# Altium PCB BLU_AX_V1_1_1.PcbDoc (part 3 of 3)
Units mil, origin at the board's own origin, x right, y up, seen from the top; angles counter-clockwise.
Board outline 2623.2 x 4215 mil, 6 copper layers (Top Layer, GND1, PWR, Signal Inner, GND2, Bottom Layer), stack 76.535 mil thick; 238 components, 119 nets, 699 pads, 786 vias.
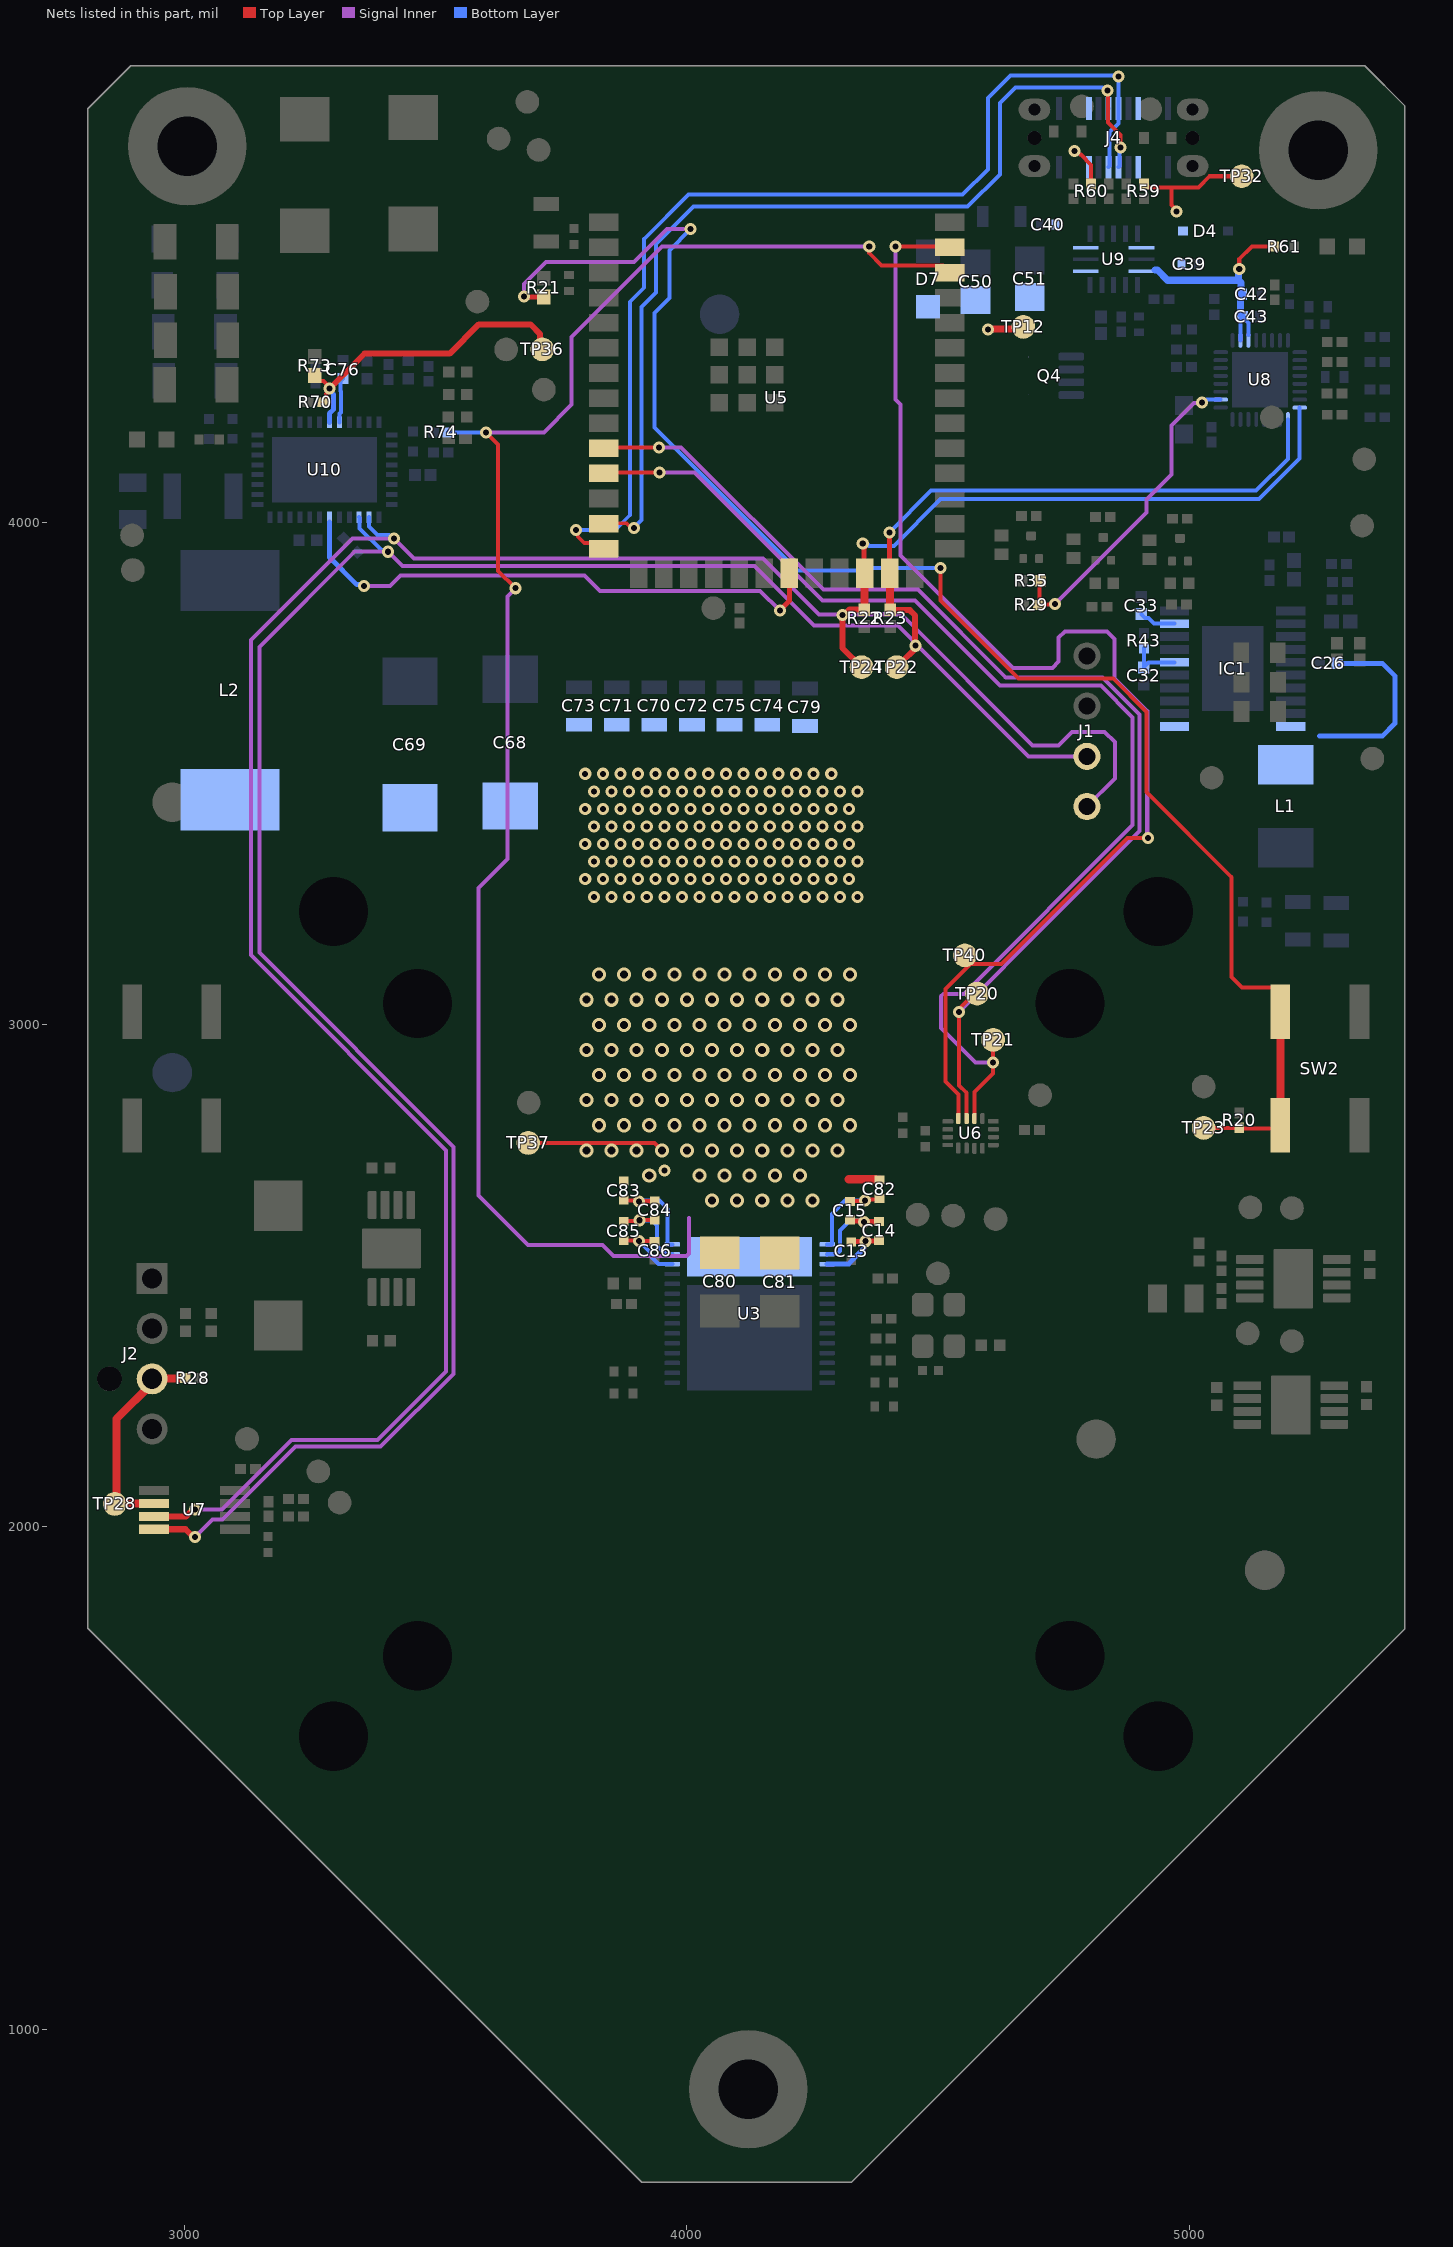
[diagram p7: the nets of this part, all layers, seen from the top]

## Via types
v1: diameter 24, hole 12, Top Layer to Bottom Layer, tented both sides, 623 vias
v2: diameter 28, hole 16, Top Layer to Bottom Layer, 146 vias
v3: diameter 19.68, hole 7.87, Top Layer to Bottom Layer, 16 vias
v4: diameter 24, hole 12, Top Layer to Bottom Layer, 1 vias

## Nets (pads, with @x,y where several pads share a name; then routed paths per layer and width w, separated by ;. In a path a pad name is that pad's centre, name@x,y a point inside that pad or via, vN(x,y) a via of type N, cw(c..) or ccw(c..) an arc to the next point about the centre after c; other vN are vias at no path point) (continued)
RST: TP40.1 U5.39 U6.12 | length 2553.2
  Top Layer w8: v1(4415,4550) 4522.48,4550 U5.39@4523.43,4549.06 ; U6.12@4540.43,2813.48 4540.43,2861.58 4515.3,2886.72 4515.3,3071.3 TP40.1@4564.95,3120.96 ; TP40.1@4553.75,3138.41 4553.75,3132.16 TP40.1@4564.95,3120.96 ; v1(4918.17,3372.49) 4877.8,3372.49 4626.26,3120.96 TP40.1@4564.95,3120.96
  Signal Inner w8: v1(4415,4550) 4415,4245.34 4424.91,4235.43 4424.91,3935.09 4649.29,3710.71 4727.88,3710.71 4740.47,3723.3 4740.47,3771.03 4752.82,3783.38 4836.62,3783.38 4851.79,3768.21 4851.79,3689.98 4916.79,3624.98 4916.79,3373.87 v1(4918.17,3372.49)
RST_IN: R20.1 R21.2 SW2.1 SW2.2 TP23.1 | length 3249.9
  Top Layer w8: v1(4505,3909.64) 4505,3845.17 4660.78,3689.39 4849.07,3689.39 4915.02,3623.44 4915.02,3463.9 5085,3293.91 5085,3095 5105.83,3074.17 5168.13,3074.17 5181.81,3060.48 SW2.2@5181.81,3026.03 ; TP23.1@5029.17,2794.7 5029.32,2794.85 5099.85,2794.85 R20.1@5100,2795 5101.43,2793.57 5175.74,2793.57 SW2.1@5181.81,2799.65
  Top Layer w10: v1(3675.72,4450.34) 3676.19,4449.87 3714.31,4449.87 R21.2@3714.79,4449.4
  Top Layer w16: SW2.1@5181.81,2799.65 SW2.2@5181.81,3026.03
  Signal Inner w8: v1(3675.72,4450.34) 3675.72,4475.72 3719.16,4519.16 3894.16,4519.16 3959.91,4584.91 v1(4007.58,4584.91)
  Bottom Layer w8: v1(4007.58,4584.91) 3965,4542.34 3965,4447.81 3935,4417.81 3935,4190 4220,3905 4358.01,3905 4362.66,3909.64 v1(4505,3909.64)
RX: TP21.1 U5.11 U6.10 | length 2360.1
  Top Layer w8: U5.11@3834.45,4099.06 3835.39,4100 v1(3945,4100) ; U6.10@4572.49,2813.48 4572.49,2865.77 4610,2903.29 v1(4610,2925) TP21.1@4610,2970
  Signal Inner w8: v1(3945,4100) 4015,4100 4270,3845 4453.83,3845 4623.36,3675.47 4824.53,3675.47 4887.54,3612.46 4887.54,3397.54 4551.6,3061.61 4510.97,3061.61 4506.28,3056.92 4506.28,2993.72 4575,2925 v1(4610,2925)
SCL: J1.3 R23.1 TP22.1 U5.25 U7.8 U8.9 U10.3 | length 5595.1
  Top Layer w10: U5.25@4403.67,3900.11 v1@4403.67,3980.63
  Top Layer w12: U7.8@2939.02,1995.4 3001.36,1995.4 3016.75,1980 v1(3020,1980) ; R23.1@4405,3826.73 4409.86,3826.73 4410.81,3825.78 4443.83,3825.78 4454.4,3815.21 4454.4,3755.6 v1(4455,3755) ; TP22.1@4420,3720 4425.35,3720 v1@4457.67,3752.33
  Top Layer w16: v1(4403.41,3980.89) v1@4403.67,3980.63 ; U5.25@4403.67,3900.11 4404.47,3899.31 4404.47,3827.26 R23.1@4405,3826.73
  Signal Inner w8: v1(3020,1980) 3055,2015 3075,2015 3220,2160 3390,2160 3535,2305 3535,2757.12 3148.35,3143.76 3148.35,3752.9 3338.48,3943.02 3403.43,3943.02 v1(3404.27,3942.19) 3433.09,3913.36 4134.96,3913.36 4253.35,3794.98 4420.82,3794.98 4448.93,3766.87 4448.93,3765.4 4455,3759.33 v1(4455,3755) 4459.33,3755 4465.86,3748.46 4466.41,3748.46 4680.56,3534.31 J1.3@4795.45,3534.31
  Bottom Layer w8: U10.3@3347.28,4011.02 3348.2,4010.1 3348.2,3988.39 3391.34,3945.25 3401.2,3945.25 v1(3404.27,3942.19) ; v1(4403.41,3980.89) 4486.29,4063.78 5133.78,4063.78 5196.86,4126.86 U8.9@5196.86,4205.72
SDA: J1.4 R22.1 TP24.1 U5.24 U7.7 U8.8 U10.2 | length 5892.8
  Top Layer w10: U5.24@4352.61,3901.17 v1@4352.61,3953.79
  Top Layer w12: U7.7@2939.02,2020.99 3002.74,2020.99 3016.75,2035 v1(3020,2035) ; v1(4309.68,3816.48) 4309.68,3750.47 TP24.1@4347.8,3712.34 ; v1@4310.17,3813.43 4323.5,3826.75 R22.1@4353.29,3826.75
  Top Layer w16: v1(4350.2,3958.37) 4350.2,3956.2 v1@4352.61,3953.79 ; U5.24@4352.61,3901.17 4353.94,3899.84 4353.62,3899.53 4353.62,3827.05 R22.1@4353.31,3826.73
  Signal Inner w8: v1(3020,2035) 3074.11,2035 3212.61,2173.5 3383.5,2173.5 3520,2310 3520,2750 3131.38,3138.62 3131.38,3766.38 3333.92,3968.92 v1(3416.74,3968.92) 3456.56,3929.1 4151.62,3929.1 4263.37,3817.36 4308.8,3817.36 v1(4309.68,3816.48) 4310.9,3817.71 4427.29,3817.71 4688.48,3556.52 4740.09,3556.52 4767.15,3583.57 4831.43,3583.57 4852.13,3562.87 4852.13,3490.99 J1.4@4795.45,3434.31
  Bottom Layer w8: U10.2@3366.97,4011.02 3366.5,4010.55 3366.5,3992.85 3384.22,3975.13 3406.2,3975.13 3412.41,3968.92 v1(3416.74,3968.92) ; v1(4350.2,3958.37) 4353.26,3955.31 4361.52,3955.31 4362.88,3953.94 4412.46,3953.94 4505.3,4046.78 5139.79,4046.78 5220.48,4127.48 U8.8@5220.48,4229.35
SINK_EN: R29.2 R35.1 U8.18 | length 675.5
  Top Layer w8: R35.1@4704,3884.43 4711.26,3877.16 4711.26,3876.86 R35.1@4703.7,3884.43 4702.18,3882.91 4702.18,3838.06 R29.2@4700.26,3836.15 4701.3,3837.18 4732.2,3837.18 v1(4733.23,3838.22)
  Signal Inner w8: v1(4733.23,3838.22) 4915,4019.99 4915,4045.93 4964.95,4095.88 4964.95,4193.46 5009.71,4238.22 5024.76,4238.22 v1(5025.88,4239.34)
  Bottom Layer w8: v1(5025.88,4239.34) 5029.55,4239.34 5035.3,4245.09 U8.18@5063,4245.09
SMB: U5.21 U10.6 | length 1110.7
  Top Layer w10: v1(4185,3825) 4185,3825.31 4203.94,3844.25 U5.21@4203.94,3899.84
  Signal Inner w8: v1(3356.89,3873.96) 3408.96,3873.96 3430,3895 3796.36,3895 3827.24,3864.11 4145.89,3864.11 v1(4185,3825)
  Bottom Layer w10: U10.6@3288.2,4000.97 3288.2,3931.1 3342.66,3876.64 3354.21,3876.64 v1(3356.89,3873.96)
SS: C33.1 IC1.19 | length 74.7
  Bottom Layer w8: C33.1@4905,3818.13 4905,3817.28 4912.27,3810.01 4918.97,3810.01 4930.15,3798.83 IC1.19@4971.19,3798.83
SW: C26.1 IC1.10 IC1.11 L1.1 | length 380.7
  Bottom Layer w10: 5260,3575 5385,3575 5410,3600 5410,3695 5385,3720 C26.1@5295,3720
TACH: J2.3 R28.1 TP28.1 U7.6 | length 424.8
  Top Layer w16: TP28.1@2860.47,2045.74 2863.64,2048.91 2863.64,2214.85 2935.63,2286.84 2935.63,2295.63 3000.37,2295.63 R28.1@3001,2296.27 ; TP28.1@2860.9,2046.65 2938.95,2046.65 U7.6@2939.02,2046.58
TPS_EN: R70.1 R73.2 TP36.1 U10.27 | length 648.4
  Top Layer w8: R73.2@3258.68,4293.41 3258.68,4292.43 3268.46,4282.65 3276.65,4282.65 3288.58,4270.72 v1(3288.58,4267.26) 3288.58,4262.93 3281.59,4255.94 3281.59,4245.84 3275.75,4240 R70.1@3274.76,4240
  Top Layer w12: v1(3288.58,4267.26) 3357.96,4336.64 3527.34,4336.64 3585.69,4395 3688.43,4395 3707.71,4375.73 3707.71,4349.8 TP36.1@3712.18,4345.33
  Bottom Layer w10: U10.27@3288.23,4200 3288.3,4200.08 3288.3,4217.87 3296.37,4225.94 3296.37,4255.25 3295.94,4255.68
TX: TP20.1 U5.10 U6.11 | length 2303
  Top Layer w8: U5.10@3834.45,4149.06 3835.19,4149.8 v1(3944.8,4149.8) ; U6.11@4556.97,2813.48 4556.64,2813.81 4556.64,2822.05 4556.37,2822.32 4556.37,2864.73 4541.45,2879.66 v1(4541.45,3025.98) 4544.51,3029.04 4544.51,3034.73 4572.13,3062.35 TP20.1@4577.82,3062.35
  Signal Inner w8: v1(3944.8,4149.8) 3945,4150 3988.43,4150 4271.58,3866.85 4460.13,3866.85 4634.99,3691.99 4828.01,3691.99 4901.6,3618.4 4901.6,3386.33 4724.46,3209.19 4724.46,3208.99 v1(4541.45,3025.98)
USB_N: J4.A7 J4.B7 U5.13 | length 1963.2
  Top Layer w7.49: U5.13@3834.45,3999.06 3879.89,3999.06 3889.74,3989.2 v1(3894.2,3989.2)
  Top Layer w8: v1(4837.66,4860.65) 4838.3,4860.01 4838.3,4796.7 4863.18,4771.82 v1(4863.18,4747.5)
  Bottom Layer w7.94: v1(3894.2,3989.2) 3910,4005 3910,4430 3938.83,4458.83 3938.83,4555.13 4013.27,4629.57 4559.14,4629.57 4623.12,4693.56 4623.12,4835.67 4654.18,4866.72 4827.24,4866.72 4830.24,4863.72 4834.59,4863.72 v1(4837.66,4860.65)
  Bottom Layer w8: v1(4837.66,4860.65) 4838.72,4859.59 4838.72,4826.02 J4.B7@4839.77,4824.97 ; J4.A7@4859.46,4708.04 4861.32,4709.9 4861.32,4745.64 v1(4863.18,4747.5)
USB_P: J4.A6 J4.B6 U5.14 | length 2107.6
  Top Layer w7.49: v1(3779.35,3985.05) 3782.51,3981.89 3782.51,3972.46 3795.38,3959.59 3823.92,3959.59 U5.14@3834.45,3949.06
  Bottom Layer w7.94: v1(3779.35,3985.05) 3856.36,3985.05 3886.17,4014.87 3886.17,4439.87 3915,4468.69 3915,4565 4003.4,4653.4 4549.27,4653.4 4599.3,4703.43 4599.3,4845.53 4644.31,4890.54 4827.24,4890.54 4857.06,4890.54 v1(4859.16,4888.44)
  Bottom Layer w8: J4.A6@4839.77,4708.04 4841.68,4709.94 4841.68,4777.79 4859.4,4795.51 J4.B6@4859.4,4824.39 ; J4.B6@4859.16,4825.27 v1(4859.16,4888.44)
V_eFuse: C42.1 C43.1 C50.1 C51.1 D7.1 Q4.7 R61.2 TP12.1 U8.26 U8.27 U9.8 U9.14 | length 539
  Top Layer w8: v1(5100,4505) 5100,4525 5125.04,4550.04 R61.2@5169.56,4550.04
  Top Layer w14: v1(4600,4385) 4600.99,4385.99 4665.99,4385.99 TP12.1@4670,4390
  Bottom Layer w8: U8.26@5102.37,4363.2 5102.44,4363.27 5102.44,4405.94 C43.1@5106.57,4410.08 5106.57,4409.99 5118.35,4398.21 5118.35,4374.14 U8.27@5118.19,4373.97
  Bottom Layer w14: 4931.79,4503.21 4937.14,4503.21 4957.47,4482.89 5098.36,4482.89 ; v1(5100,4505) 5098.36,4503.36 5098.36,4482.89 ; C43.1@5106.57,4410.08 5102.24,4414.41 5102.24,4450.94 C42.1@5106.3,4455 5103.05,4458.25 5103.05,4478.2 5098.36,4482.89
VBUS: C39.1 C40.1 D4.1 J4.A4 J4.A9 J4.B4 J4.B9 R59.2 R60.2 TP32.1 U9.6 U9.16 | length 342.3
  Top Layer w8: v1(4771.76,4740.26) 4776.09,4740.26 4783.02,4733.33 4784.49,4733.33 4805,4712.81 R60.2@4805,4674.76 ; R59.2@4910,4674.76 4910,4673.78 4915.84,4667.94 4965,4667.94 ; v1(4975,4620) 4975,4622.69 4965,4632.69 4965,4667.94 ; TP32.1@5105,4690 5040.8,4690 5018.73,4667.94 4965,4667.94
VCORE: C68.1 C69.1 C70.1 C71.1 C72.1 C73.1 C74.1 C75.1 C79.1 C80.2 C81.2 C82.2 C83.1 L2.2 R74.2 TP37.1 U3.31 U5.38 | length 3717
  Top Layer w8: v1(3600,4180) 3624.15,4155.85 3624.15,3903.79 v1(3658.42,3869.52) ; TP37.1@3684.04,2764.7 3935.3,2764.7 v2@3955,2745 ; v1(4363.13,4550.36) 4363.13,4536.87 4387.3,4512.7 4493.24,4512.7 4493.38,4512.56 4509.93,4512.56 U5.38@4523.43,4499.06
  Top Layer w17: 4322.7,2692.73 4375.61,2692.73 4376.48,2691.87 4383.16,2691.87 C82.2@4383.52,2691.51
  Signal Inner w8: v1(3600,4180) 3715,4180 3770,4235 3770,4370 3950.36,4550.36 v1(4363.13,4550.36) ; v1(3658.42,3869.52) 3642.33,3853.43 3642.33,3330.32 3584.87,3272.87 3584.87,2660.07 3683.34,2561.6 3831.81,2561.6 3853.51,2539.9 3999.48,2539.9 4004.17,2544.59 4004.17,2615
  Bottom Layer w8: R74.2@3524.53,4180 v1(3600,4180)
  other v1: 3955,2710 3815,3255 3850,3255 3885,3255 3920,3255 3955,3255 3990,3255 4025,3255 4060,3255 4095,3255 4130,3255 4165,3255 4200,3255 4235,3255 4270,3255 4305,3255 4340,3255 3797.5,3290 3832.5,3290 3867.5,3290 3902.5,3290 3937.5,3290 3972.5,3290 4007.5,3290 4042.5,3290 4077.5,3290 4112.5,3290 4147.5,3290 4182.5,3290 4217.5,3290 4252.5,3290 4287.5,3290 4322.5,3290 3815,3325 3850,3325 3885,3325 3920,3325 3955,3325 3990,3325 4025,3325 4060,3325 4095,3325 4130,3325 4165,3325 4200,3325 4235,3325 4270,3325 4305,3325 4340,3325 3797.5,3360 3832.5,3360 3867.5,3360 3902.5,3360 3937.5,3360 3972.5,3360 4007.5,3360 4042.5,3360 4077.5,3360 4112.5,3360 4147.5,3360 4182.5,3360 4217.5,3360 4252.5,3360 4287.5,3360 4322.5,3360 3815,3395 3850,3395 3885,3395 3920,3395 3955,3395 3990,3395 4025,3395 4060,3395 4095,3395 4130,3395 4165,3395 4200,3395 4235,3395 4270,3395 4305,3395 4340,3395 3797.5,3430 3832.5,3430 3867.5,3430 3902.5,3430 3937.5,3430 3972.5,3430 4007.5,3430 4042.5,3430 4077.5,3430 4112.5,3430 4147.5,3430 4182.5,3430 4217.5,3430 4252.5,3430 4287.5,3430 4322.5,3430 3815,3465 3850,3465 3885,3465 3920,3465 3955,3465 3990,3465 4025,3465 4060,3465 4095,3465 4130,3465 4165,3465 4200,3465 4235,3465 4270,3465 4305,3465 4340,3465 3797.5,3500 3832.5,3500 3867.5,3500 3902.5,3500 3937.5,3500 3972.5,3500 4007.5,3500 4042.5,3500 4077.5,3500 4112.5,3500 4147.5,3500 4182.5,3500 4217.5,3500 4252.5,3500 4287.5,3500
  other v2: 4050,2650 4100,2650 4150,2650 4200,2650 4250,2650 3925,2700 4025,2700 4075,2700 4125,2700 4175,2700 4225,2700 3800,2750 3850,2750 3900,2750 3950,2750 4000,2750 4050,2750 4100,2750 4150,2750 4200,2750 4250,2750 4300,2750 3825,2800 3875,2800 3925,2800 3975,2800 4025,2800 4075,2800 4125,2800 4175,2800 4225,2800 4275,2800 4325,2800 3800,2850 3850,2850 3900,2850 3950,2850 4000,2850 4050,2850 4100,2850 4150,2850 4200,2850 4250,2850 4300,2850 3825,2900 3875,2900 3925,2900 3975,2900 4025,2900 4075,2900 4125,2900 4175,2900 4225,2900 4275,2900 4325,2900 3800,2950 3850,2950 3900,2950 3950,2950 4000,2950 4050,2950 4100,2950 4150,2950 4200,2950 4250,2950 4300,2950 3825,3000 3875,3000 3925,3000 3975,3000 4025,3000 4075,3000 4125,3000 4175,3000 4225,3000 4275,3000 4325,3000 3800,3050 3850,3050 3900,3050 3950,3050 4000,3050 4050,3050 4100,3050 4150,3050 4200,3050 4250,3050 4300,3050 3825,3100 3875,3100 3925,3100 3975,3100 4025,3100 4075,3100 4125,3100 4175,3100 4225,3100 4275,3100 4325,3100
VDD1_1: C15.2 C82.1 U3.1 | length 208.6
  Top Layer w8: C15.2@4324.57,2648.38 4325.28,2649.09 4354.21,2649.09 4357.08,2651.96 4381.37,2651.96 C82.1@4383.52,2654.11
  Bottom Layer w8: U3.1@4279.17,2562.8 4288.12,2562.8 4288.55,2563.22 4288.55,2623.55 4315,2650 4354.73,2650 v1(4354.93,2649.81)
VDD1_2: C14.2 C15.1 U3.2 | length 185.4
  Top Layer w10: C15.1@4324.57,2610.98 4326.28,2609.27 4351.29,2609.27 v1(4353,2607.55) 4353.29,2607.84 4381.05,2607.84 C14.2@4382.03,2608.81
  Bottom Layer w8: U3.2@4279.17,2543.11 4279.6,2543.54 4298.54,2543.54 4305,2550 4305,2590 4325,2610 4350.56,2610 v1(4353,2607.55)
VDD1_3: C13.2 C14.1 U3.3 | length 158.8
  Top Layer w10: C13.2@4327.32,2567.75 4327.96,2568.38 4354.83,2568.38 4356.31,2569.87 4381.86,2569.87 C14.1@4382.71,2570.72
  Bottom Layer w10: U3.3@4279.17,2523.43 4279.74,2524 4322.38,2524 4352.78,2554.39 4352.78,2566.34 v1(4355.46,2569.02)
VDD2_1: C83.2 C84.1 U3.30 | length 207.9
  Top Layer w8: C83.2@3874.3,2651.32 3875.84,2649.78 3902.71,2649.78 v1(3904.25,2648.24) 3904.67,2648.66 3935.5,2648.66 C84.1@3935.91,2649.07
  Bottom Layer w8: v1(3904.25,2648.24) 3906.01,2650 3945,2650 3961.45,2633.55 3961.45,2563.22 3961.88,2562.8 U3.30@3970.83,2562.8
VDD2_2: C84.2 C85.1 U3.29 | length 179.4
  Top Layer w8: C85.1@3874.42,2609.33 3874.51,2609.43 3903.97,2609.43 3905.79,2611.25 3935.5,2611.25 C84.2@3935.91,2611.67
  Bottom Layer w8: v1(3905.37,2610.83) 3905.58,2610.63 3929.37,2610.63 3940,2600 3940,2560 3951.13,2548.87 3953.91,2548.87 3959.67,2543.11 U3.29@3970.83,2543.11
VDD2_3: C85.2 C86.1 U3.28 | length 152.2
  Top Layer w8: C85.2@3874.26,2570.62 3874.63,2570.25 3904.25,2570.25 3905.21,2569.29 3935.09,2569.29 C86.1@3935.67,2568.71
  Bottom Layer w8: v1(3904.63,2569.87) 3925.46,2549.04 3925.46,2541.2 3943.24,2523.43 U3.28@3970.83,2523.43
VDD5: C76.1 U10.28 | length 90.8
  Bottom Layer w8: U10.28@3307.91,4200 3308.27,4200.38 3308.27,4217.34 3310.87,4219.93 3310.87,4261.69 3310.08,4262.48 3310.08,4282.28 C76.1@3315,4287.2
VDD_MP: C32.1 IC1.16 R43.2 | length 103.4
  Bottom Layer w8: C32.1@4910,3711.87 C32.1@4910,3712.72 ; R43.2@4910,3750.24 C32.1@4910,3712.72 ; IC1.16@4971.19,3722.06 4919.34,3722.06 C32.1@4910,3712.72
pads on no net: FD1.0 FD2.0 FD3.0 FD4.0 FD5.0 FD6.0 IC1.9 IC1.12 IC1.17 J2. J4. J4.A8 J4.B8 Q4.2 Q4.3 U1.3 U1.7 U2.3 U2.7 U3.12 U3.19 U4.3 U4.7 U5.4 U5.5 U5.6 U5.7 U5.8 U5.9 U5.12 U5.16 U5.17 U5.18 U5.20 U5.22 U5.26 U5.28 U5.29 U5.30 U5.31 U5.32 U5.33 U5.34 U5.35 U6.9 U9.5 U10.35 U10.36 U10.38 U10.39 U10.40

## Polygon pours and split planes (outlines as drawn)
DGND on Top Layer "pour" (solid, pour order 65): 2870,3665 2870,1835 3960,745 4275,745 5390,1860 5390,2955 5250,3095 4930,3095 4375,3650
DGND on Top Layer "NONET_L-01_P-001" (solid, pour order 47): 5119.65,3603.36 5036.64,3603.36 5015,3625 5015,3805 5135,3805 5148.13,3791.87 5148.13,3613.13 5140,3605
VCORE on Top Layer "NONET_L-01_P-001" (solid, pour order 57): 3999.2,2578.72 3999.54,2578.37 3999.54,2500.28 4249.17,2500.28 4248.83,2500.62 4248.83,2610.56 4369.78,2731.51 4369.78,3466.51 4289.78,3546.51 3764.78,3546.51 3764.78,2746.51 3829.78,2681.51 3954.78,2681.51 3979.78,2656.51 3979.78,2599.27 3999.57,2579.47
DGND on Top Layer "NONET_L-01_P-001" (solid, pour order 54): 4001.09,2273.43 3866.09,2138.43 3866.09,1930 4396.09,1930 4396.09,2143.43 4251.09,2288.43 4251.09,2473.43 4241.09,2483.43 4011.09,2483.43 4001.09,2473.43
3V3_IN on Top Layer "NONET_L-01_P-001" (solid, pour order 0): 3030,4225 3030,4575 3095,4640 3510,4640 3530,4620 3530,4535 3510,4515 3510,4410 3490,4390 3220,4390 3220,4280 3240,4260 3255,4260 3260,4255 3260,4225 3255,4220 3255,4190 3165,4190 3155,4200 3055,4200
3V3_IN on Top Layer "NONET_L-01_P-001" (solid, pour order 42): 5160,3765 5160,3605 5260,3605 5275,3590 5360,3590 5395,3625 5395,3690 5310,3690 5305,3695 5305,3740 5285,3740 5285,3715 5260,3715 5210,3765 5190,3765
3V3_IN on Top Layer "NONET_L-01_P-001" (solid, pour order 25): 3310,2610 3275,2645 3275,2730 3305,2760 3375,2760 3385,2750 3385,2610
DGND on Top Layer "NONET_L-01_P-001" (solid, pour order 24): 2895,2455 2950,2455 2990,2415 3060,2415 3155,2510 3475,2510 3485,2520 3485,2590 3475,2600 3295,2600 3245,2650 3245,2700 3240,2705 3130,2705 3110,2685 3110,2600 3055,2545 2900,2545 2880,2525 2880,2470
1V2 on Top Layer "NONET_L-01_P-001" (solid, pour order 15): 5080,2525 5075,2530 5055,2530 5030,2555 4985,2555 4975,2565 4975,2610 4995,2630 5075,2630 5105,2600 5140,2600 5150,2590 5150,2525
DGND on Top Layer "NONET_L-01_P-001" (solid, pour order 22): 3565,4855 3545,4875 2920,4875 2845,4800 2845,4140 2865,4120 2915,4120 2935,4140 2935,4195 2965,4225 2990,4225 2990,4575 3085,4670 3510,4670 3565,4725
FS on Top Layer "NONET_L-01_P-001" (solid, pour order 21): 3350,2500 3305,2455 3130,2455 3100,2425 3100,2410 3090,2400 2990,2400 2955,2435 2910,2435 2890,2415 2890,2375 2915,2350 2970,2350 2990,2370 3080,2370 3105,2345 3380,2345 3395,2360 3395,2410 3410,2425 3410,2500
DGND on Top Layer "NONET_L-01_P-001" (solid, pour order 20): 4040,4210 4065,4185 4225,4185 4240,4200 4240,4365 4225,4380 4040,4380
DGND on Top Layer "NONET_L-01_P-001" (solid, pour order 19): 4410,4580 4385,4605 4385,4620 4555,4620 4555,4580
3V3_ESP on Top Layer "NONET_L-01_P-001" (solid, pour order 18): 3635,4530 3605,4560 3605,4620 3620,4635 3670,4635 3675,4630 3675,4575
3V3_ESP on Top Layer "NONET_L-01_P-001" (solid, pour order 16): 3895,4530 3635,4530 3630,4535 3630,4585 3740,4585 3760,4565 3800,4565 3805,4570 3885,4570 3895,4560
DGND on Top Layer "NONET_L-01_P-001" (solid, pour order 17): 3895,4580 3795,4580 3790,4575 3765,4575 3740,4600 3690,4600 3685,4605 3685,4665 3868.33,4665 3895,4625
3V3_ESP on Top Layer "NONET_L-01_P-001" (solid, pour order 14): 5266.32,2584.93 5281.32,2599.93 5391.32,2599.93 5406.32,2584.93 5406.32,2534.93 5391.32,2519.93 5331.32,2519.93 5326.32,2524.93 5266.32,2524.93
0V8_REF on Top Layer "NONET_L-01_P-001" (solid, pour order 13): 5065,2265 4995,2265 4975,2285 4975,2335 4995,2355 5120,2355 5145,2330 5145,2270 5075,2270
3V3_ESP on Top Layer "NONET_L-01_P-001" (solid, pour order 12): 5265,2330 5280,2345 5390,2345 5405,2330 5405,2280 5390,2265 5330,2265 5325,2270 5265,2270
DGND on Top Layer "NONET_L-01_P-001" (solid, pour order 11): 4526.63,2780.67 4526.4,2780.91 4503.21,2780.91 4489.85,2767.55 4465.01,2767.55 4463.08,2765.63 4463.08,2706.92 4465,2705 4498.19,2705 4530,2736.8 4530,2780.55
DGND on Bottom Layer "pour" (solid, pour order 68): 2870,3665 2870,1835 3960,745 4275,745 5390,1860 5390,2955 5250,3095 4930,3095 4375,3650
DGND on Bottom Layer "NONET_L-01_P-001" (solid, pour order 64): 4745,4800 4665,4800 4655,4810 4655,4845 4665,4855 4745,4855
3V3_IN on Bottom Layer "NONET_L-01_P-001" (solid, pour order 1): 3255,4185 3160,4185 3155,4190 3155,4195 3030,4195 3030,4575 3095,4640 3480,4640 3505,4615 3505,4405 3495,4395 3235,4395 3235,4265 3245,4255 3255,4255 3255,4210
DGND on Bottom Layer "NONET_L-01_P-001" (solid, pour order 61): 5009.16,4505.55 5009.54,4505.94 5009.54,4612.94 4979.33,4643.15 4961.57,4643.15 4951.27,4653.45 4951.27,4664.51 5064.79,4664.51 5068.39,4660.91 5068.39,4615.09 5073.8,4615.09 5100.57,4588.32 5100.57,4553.06 5052.43,4504.92 5031.32,4504.92
3V3_IN on Bottom Layer "NONET_L-01_P-001" (solid, pour order 60): 4675,4075 4915,4075 4945,4105 4945,4205 4950,4210 5015,4210 5015,4245 5025,4255 5025,4265 4875,4265 4840,4230 4735,4230 4725,4240 4715,4230 4670,4230
DGND on Bottom Layer "NONET_L-01_P-001" (solid, pour order 45): 5170,3215 5175,3210 5175,3195 5185,3185 5380,3185 5390,3175 5390,3085 5380,3075 5090,3075 5075,3090 5075,3200 5090,3215
3V3_ESP on Bottom Layer "NONET_L-01_P-001" (solid, pour order 59): 5080,3415 4975,3415 4965,3405 4965,3355 4970,3350 5005,3350 5035,3320 5035,3295 5055,3275 5080,3275
VCORE on Bottom Layer "NONET_L-01_P-001" (solid, pour order 56): 3999.42,2577.2 3999.76,2576.86 3999.76,2498.77 4249.39,2498.77 4249.05,2499.11 4249.05,2609.05 4370,2730 4370,3465 4290,3545 3765,3545 3765,2745 3830,2680 3955,2680 3980,2655 3980,2597.76 3999.8,2577.96
DGND on Bottom Layer "NONET_L-01_P-001" (solid, pour order 53): 4000,2270 3865,2135 3865,1930 4395,1930 4395,2140 4250,2285 4250,2470 4240,2480 4010,2480 4000,2470
3V3_IN on Bottom Layer "NONET_L-01_P-001" (solid, pour order 51): 4723.51,4286.94 4560,4286.94 4560,4075 4675,4075 4725,4125 4725,4225
3V3_IN on Bottom Layer "NONET_L-01_P-001" (solid, pour order 46): 5175,3705 5295,3705 5305,3695 5385,3695 5395,3685 5395,3625 5355,3585 5280,3585 5245,3620 5245,3635 5175,3635
3V3_ESP on Bottom Layer "NONET_L-01_P-001" (solid, pour order 44): 5185,3225 5185,3205 5195,3195 5360,3195 5370,3205 5370,3240 5200,3240
3V3_ESP on Bottom Layer "NONET_L-01_P-001" (solid, pour order 43): 5055,3275 5055,3410 5060,3415 5360,3415 5385,3390 5385,3255 5355,3225 5105,3225
SW on Bottom Layer "NONET_L-01_P-001" (solid, pour order 41): 4940,3605 5250,3605 5265,3590 5265,3470 5250,3455 5130,3455 5055,3530 4940,3530
DGND on Bottom Layer "NONET_L-01_P-001" (solid, pour order 40): 4942.28,3705.18 4942.46,3705 5010,3705 5020,3715 5050,3715 5050,3630 5045,3625 5015,3625 5003.73,3636.27 4941.62,3636.27
DGND on Bottom Layer "NONET_L-01_P-001" (solid, pour order 39): 5141.9,4195.39 5141.9,4235.39 5146.9,4240.39 5166.9,4240.39 5171.9,4235.39 5171.9,4190.39 5166.9,4185.39 5146.9,4185.39
DGND on Bottom Layer "NONET_L-01_P-001" (solid, pour order 38): 5079.13,4192.45 5079.13,4219.13 5085,4225 5085,4240 5115,4240 5125,4230 5125,4185 5080,4185
DGND on Bottom Layer "NONET_L-01_P-001" (solid, pour order 36): 5130,4470 5155,4470 5155,4325 5130,4325
V_eFuse on Bottom Layer "NONET_L-01_P-001" (solid, pour order 35): 4884.67,4493.86 4950,4490 4947.2,4507.2 4932.93,4512.72 4930.54,4515.11 4923.04,4515.11
V_eFuse on Bottom Layer "NONET_L-01_P-001" (solid, pour order 34): 4938.47,4515 4745,4515 4730,4500 4730,4485 4720,4475 4465,4475 4450,4460 4450,4310 4462.43,4297.57 4727.57,4297.57 4730,4300 4730,4355 4775,4355 4795,4375 4795,4430 4785,4440 4785,4491.45 4795,4490 4805.18,4490 4880.14,4490
DGND on Bottom Layer "NONET_L-01_P-001" (solid, pour order 33): 4951.88,4802.54 5043.01,4802.54 5055,4814.53 5055,4855 5050,4860 4955,4860 4950,4855
DGND on Bottom Layer "NONET_L-01_P-001" (solid, pour order 31): 4650,4495 4650,4670 4660,4680 4695,4680 4710,4665 4710,4495
DGND on Bottom Layer "NONET_L-01_P-001" (solid, pour order 30): 4746.89,4731.64 4746.29,4732.24 4652.24,4732.24 4645,4725 4645,4675 4655,4665 4733.34,4665 4747.04,4678.7
DGND on Bottom Layer "NONET_L-01_P-001" (solid, pour order 29): 4946.94,4735 5055,4735 5070,4720 5070,4660 5065,4655 4960,4655 4946.94,4668.06
VBUS on Bottom Layer "NONET_L-01_P-001" (solid, pour order 26): 4970,4533.16 4970,4505 5005,4505 5005,4610 4980,4635 4950,4635 4945,4640 4945,4850 4940,4855 4895,4855 4890,4850 4890,4620 4900,4610 4920,4610 4925,4605 4925,4575 4905,4555 4870,4555 4870,4533.16
VBUS on Bottom Layer "NONET_L-01_P-001" (solid, pour order 27): 4905.36,4533.33 4741.67,4533.33 4725,4550 4725,4655 4740,4655 4760,4675 4760,4855 4765,4860 4804.66,4860 4810,4854.66 4804.66,4690 4790,4615 4790,4565 4790,4555 4905.36,4555
BP1V5 on Bottom Layer "NONET_L-01_P-001" (solid, pour order 23): 3330,3940 3345,3925 3345,3910 3373.33,3881.67 3410,3880 3408.12,3916.87 3380,3945 3355,3945 3343.92,3956.08
DGND on Bottom Layer "NONET_L-01_P-001" (solid, pour order 10): 4260,3655 3740,3655 3740,3635 3685,3580 3405,3580 3345,3640 3345,3805 3395,3855 3825,3855 3920,3760 4260,3760
VCORE on Bottom Layer "NONET_L-01_P-001" (solid, pour order 8): 3350,3385 3440,3295 4220,3295 4320,3395 4320,3620 4305,3635 3755,3635 3710,3590 3710,3570 3385,3570 3275,3680 2875,3680 2840,3645 2840,3410 2865,3385
NetC55_2 on Bottom Layer "NONET_L-01_P-001" (solid, pour order 7): 3255,4025 3255,3995 3245,3985 3245,3755 3215,3725 2900,3725 2840,3785 2840,4000 2865,4025 3148.26,4025 3161.67,4035 3250,4035
DGND on Bottom Layer "NONET_L-01_P-001" (solid, pour order 2): 3010,4000 3010,4120 2865,4120 2845,4140 2845,4805 2915,4875 3540,4875 3565,4850 3565,4755 3510,4700 3130,4700 3050,4620 3005,4620 2990,4605 2990,4205 3015,4180 3150,4180 3155,4175 3160,4175 3160,4060 3130,4030 3130,4000
DGND on Bottom Layer "NONET_L-01_P-001" (solid, pour order 3): 3155,4025 3155,4027.83 3167.17,4040 3385,4040 3390,4045 3390,4170 3385,4175 3157.5,4175 3152.5,4180 3130,4180 3130,4030
AGND on Bottom Layer "NONET_L-01_P-001" (solid, pour order 4): 3345,4310 3390,4310 3395,4305 3470,4305 3475,4300 3540,4300 3560,4280 3560,4225 3590,4225 3615,4200 3615,4160 3566.64,4107.05 3481.77,4107.05 3481.77,4083.43 3638.43,4083.43 3660,4105 3660,4315 3585,4390 3345,4390
NetC66_2 on Bottom Layer "NONET_L-01_P-001" (solid, pour order 6): 2870,4110 2990,4110 3000,4100 3000,4000 2995,3995 2960,3995 2955,4000 2955,4045 2950,4050 2865,4050 2860,4055 2860,4105
DGND on Signal Inner "NONET_L-01_P-001" (solid, pour order 71): 3660,3800 3660,3320 3610,3270 3610,2675 3710,2575 4015,2575 4040,2550 4040,2295 3965,2220 3865,2220 3865,1925 3915,1875 3914.93,1874.93 3914.93,1664.93 3815,1565 3815,1230 4015,1030 4540,1030 5375,1865 5375,4815 5310,4880 4595,4880 4595,4840 4595,4815 4595,4675 4470,4550 4095,4550 4095,4505 3670,4080 3670,4005
DGND on Signal Inner "NONET_L-01_P-001" (solid, pour order 70): 3580,3855 2985,3855 2840,3710 2840,1835 3360,1315 3720,1315 3765,1360 3765,2315 3540,2540 3540,3300 3600,3360 3600,3828.33
VCORE on Signal Inner "NONET_L-01_P-001" (solid, pour order 62): 3999.21,2578.7 3999.55,2578.36 3999.55,2500.27 4249.18,2500.27 4248.84,2500.61 4248.84,2610.55 4369.79,2731.5 4369.79,3466.5 4289.79,3546.5 3764.79,3546.5 3764.79,2746.5 3829.79,2681.5 3954.79,2681.5 3979.79,2656.5 3979.79,2599.26 3999.59,2579.46
DGND on GND2 (split plane): 3815,4691.13 3623.07,4691.13 3621.9,4690.89 3620.9,4690.23 3577.84,4647.16 3577.17,4646.17 3576.94,4645 3576.94,4535 3577.17,4533.83 3577.84,4532.84 3629.7,4480.97 3630.7,4480.31 3631.87,4480.08 4200.6,4480.08 4255.98,4424.7 4255.98,4341.27 4256.21,4340.1 4256.29,4339.97 4256.29,4327.85 4256.53,4326.68 4257.19,4325.68 4258.18,4325.02 4259.35,4324.79 5197.85,4324.79 5199.02,4325.02 5200.01,4325.68 5201.94,4327.62 5201.94,3480 5201.94,3476.27 5168.73,3443.06 4915,3443.06 4913.83,3442.83 4912.84,3442.16 4897.84,3427.16 4897.17,3426.17 4896.94,3425 4896.94,3335 4897.17,3333.83 4897.84,3332.84 4912.84,3317.84 4913.83,3317.17 4915,3316.94 4973.73,3316.94 5026.94,3263.73 5026.94,3260 5027.17,3258.83 5027.84,3257.84 5057.84,3227.84 5058.83,3227.17 5060,3226.94 5409.9,3226.94 5409.9,1805.43 4319.57,715.1 3918.32,715.1 2826.9,1806.53 2826.9,4816.11 2900.69,4889.9 3815,4889.9
3V3_ESP on GND2 (split plane): 3815,4660 4380.67,4660 4402.84,4637.84 4537.84,4502.84 4538.83,4502.17 4540,4501.94 5378.73,4501.94 5409.9,4470.77 5409.9,3234.23 5408.73,3233.06 5061.27,3233.06 5033.06,3261.27 5033.06,3265 5032.83,3266.17 5032.16,3267.16 4977.16,3322.16 4976.17,3322.83 4975,3323.06 4916.27,3323.06 4903.06,3336.27 4903.06,3423.73 4916.27,3436.94 5170,3436.94 5171.17,3437.17 5172.16,3437.84 5207.16,3472.84 5207.83,3473.83 5208.06,3475 5208.06,3480 5208.06,4335 5207.83,4336.17 5207.16,4337.16 5206.17,4337.83 5205,4338.06 5203.83,4337.83 5202.84,4337.16 5196.58,4330.91 4262.41,4330.91 4262.41,4340.95 4262.18,4342.12 4262.09,4342.25 4262.09,4425.96 4261.86,4427.14 4261.2,4428.13 4204.03,4485.3 4203.04,4485.96 4201.87,4486.19 3633.13,4486.19 3583.06,4536.27 3583.06,4643.73 3624.33,4685.01 3815,4685.01
VCORE on GND2 (split plane): 4302.84,3532.84 4303.83,3532.17 4305,3531.94 4308.73,3531.94 4371.94,3468.73 4371.94,3390 4371.94,2736.27 4327.84,2692.16 4252.84,2617.16 4252.17,2616.17 4251.94,2615 4251.94,2506.27 4248.73,2503.06 4003.06,2503.06 4003.06,2580 4002.83,2581.17 4002.16,2582.16 3983.06,2601.27 3983.06,2655 3982.83,2656.17 3982.16,2657.16 3957.16,2682.16 3956.17,2682.83 3955,2683.06 3826.27,2683.06 3763.06,2746.27 3763.06,3546.94 4288.73,3546.94
DGND on GND2 (split plane): 5409.9,4821.68 5409.9,4479.42 5382.16,4507.16 5381.17,4507.83 5380,4508.06 4541.27,4508.06 4407.16,4642.16 4389.33,4660 4545,4660 4545,4889.9 5341.68,4889.9
3V3_ESP on PWR (split plane): 5409.9,4821.68 5409.9,1805.43 4319.57,715.1 3918.32,715.1 2826.9,1806.53 2826.9,4816.11 2900.69,4889.9 3815,4889.9 3815,4660 4545,4660 4545,4889.9 5341.68,4889.9
3V3_IN on PWR (split plane): 3812.84,4517.84 3813.83,4517.17 3815,4516.94 4193.73,4516.94 4317.84,4392.84 4318.83,4392.17 4320,4391.94 4721.94,4391.94 4721.94,4305 4721.94,4240 4722.17,4238.83 4722.84,4237.84 4732.84,4227.84 4733.83,4227.17 4735,4226.94 4840.5,4226.94 4841.67,4227.17 4842.66,4227.84 4875.54,4260.71 4941.94,4260.71 4941.94,4071.27 4928.73,4058.06 4915,4058.06 4913.83,4057.83 4912.84,4057.16 4897.84,4042.16 4897.17,4041.17 4896.94,4040 4896.94,3966.37 4897.17,3965.2 4897.84,3964.2 5019.2,3842.84 5020.2,3842.17 5021.37,3841.94 5115.93,3841.94 5250.04,3707.84 5251.03,3707.17 5252.2,3706.94 5382.8,3706.94 5382.8,3582.12 5378.73,3578.06 5210.18,3578.06 5170.01,3618.23 5169.02,3618.89 5167.85,3619.12 5025.2,3619.12 4878.06,3766.27 4878.06,3770 4877.83,3771.17 4877.16,3772.16 4847.16,3802.16 4846.17,3802.83 4845,3803.06 4721.27,3803.06 4567.16,3957.16 4467.16,4057.16 4466.17,4057.83 4465,4058.06 3826.27,4058.06 3642.16,4242.16 3498.19,4386.14 3497.2,4386.8 3496.03,4387.03 3223.17,4387.03 3221.99,4386.8 3221,4386.14 3220.34,4385.14 3220.11,4383.97 3220.11,4281.83 3220.34,4280.66 3221,4279.67 3242.84,4257.84 3243.83,4257.17 3245,4256.94 3253.73,4256.94 3256.94,4253.73 3256.94,4226.27 3252.84,4222.16 3252.17,4221.17 3251.94,4220 3251.94,4193.06 3166.27,4193.06 3157.16,4202.16 3156.17,4202.83 3155,4203.06 3056.27,4203.06 3052.16,4207.16 3033.06,4226.27 3033.06,4573.73 3042.16,4582.84 3096.27,4636.94 3693.73,4636.94
DGND on PWR (split plane): 4251.49,2287.41 4251.72,2286.24 4252.39,2285.25 4272.01,2265.62 4272.24,2265.47 4298.96,2238.74 4299.19,2238.6 4345.16,2192.62 4346.06,2192.02 4386.45,2151.64 4386.45,2151.63 4396.94,2141.14 4396.94,1938.06 3863.06,1938.06 3863.06,2115 3863.06,2133.73 3922.16,2192.84 3982.16,2252.84 3998.46,2269.13 3999.12,2270.13 3999.36,2271.3 3999.36,2479.67 3999.42,2480.01 3999.42,2483.23 4251.49,2483.23
VCORE on PWR (split plane): 4369.29,3467.68 4369.29,3452.72 4369.29,2731.34 4361.11,2723.16 4360.19,2722.97 4359.2,2722.31 4269.72,2632.83 4268.62,2632.61 4267.62,2631.95 4247.84,2612.16 4247.17,2611.17 4246.94,2610 4246.94,2503.06 4003.06,2503.06 4003.06,2575 4002.83,2576.17 4002.16,2577.16 3992.16,2587.16 3983.06,2596.27 3983.06,2655 3982.83,2656.17 3982.16,2657.16 3957.16,2682.16 3956.17,2682.83 3955,2683.06 3831.27,2683.06 3812.16,2702.16 3763.06,2751.27 3763.06,2780 3763.06,3546.94 4290.04,3546.94
1V2 on PWR (split plane): 4562.84,2787.84 4563.83,2787.17 4565,2786.94 4688.73,2786.94 4696.94,2778.73 4696.94,2745 4697.17,2743.83 4697.84,2742.84 4798.72,2641.96 4799.71,2641.29 4800.88,2641.06 5084.61,2641.06 5086.94,2638.73 5086.94,2421.27 5060.08,2394.41 4744.74,2394.41 4743.57,2394.17 4742.57,2393.51 4497.12,2148.06 4401.02,2148.06 4377.65,2171.43 4377.02,2172.37 4342.23,2207.16 4342.04,2207.29 4313.06,2236.27 4313.06,2275 4312.83,2276.17 4312.16,2277.16 4293.06,2296.27 4293.06,2436.94 4340,2436.94 4341.17,2437.17 4342.16,2437.84 4402.16,2497.84 4402.83,2498.83 4403.06,2500 4403.06,2528.73 4407.16,2532.84 4407.83,2533.83 4408.06,2535 4408.06,2673.73 4448.92,2714.59 4449.58,2715.58 4449.81,2716.75 4449.81,2825.49 4471.27,2846.94 4503.73,2846.94
DGND on GND1 (split plane): 5409.9,4821.68 5409.9,1805.43 4319.57,715.1 3918.32,715.1 2826.9,1806.53 2826.9,4816.11 2900.69,4889.9 3815,4889.9 3815,4660 4545,4660 4545,4889.9 5341.68,4889.9
VCORE on GND1 (split plane): 4318.87,3518.16 4319.86,3517.5 4320.22,3517.43 4369.32,3468.33 4369.32,2731.12 4333.74,2695.55 4333.39,2695.48 4332.4,2694.82 4253.07,2615.49 4252.45,2614.57 4249.38,2611.49 4248.72,2610.5 4248.49,2609.33 4248.49,2503.86 4000.34,2503.86 4000.34,2577.72 4000.11,2578.89 3999.44,2579.88 3978.06,2601.27 3978.06,2660 3977.83,2661.17 3977.16,2662.16 3957.16,2682.16 3956.17,2682.83 3955,2683.06 3830.17,2683.06 3825.76,2687.47 3825.46,2687.92 3781.56,2731.81 3780.66,2732.42 3769.2,2743.88 3768.89,2744.33 3765.17,2748.06 3765.17,3546.94 4290.09,3546.94

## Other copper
Top Layer:
  region: 3967.5,1652.89 3965.3,1654.69 3963.11,1655.69 3959.92,1656.88 3958.72,1658.08 3957.92,1658.48 3957.12,1659.28 3953.53,1661.27 3951.54,1663.27 3950.74,1663.67 3949.74,1664.27 3949.34,1665.06 3945.35,1669.05 3944.96,1669.85 3943.16,1672.05 3942.56,1672.25 3942.16,1673.04 3940.17,1676.63 3938.17,1679.43 3937.57,1681.62 3936.58,1684.21 3934.98,1685.81 3934.18,1687.81 3932.79,1693.99 3932.19,1696.18 3930.59,1701.37 3930.19,1702.97 3929.79,1712.94 3929.6,1840.81 3930.59,1842.21 3932.79,1842.81 3937.97,1842.41 3981.06,1842.01 3981.66,1841.41 3982.06,1839.82 3981.66,1835.83 3982.06,1724.91 3982.46,1723.71 3982.86,1718.53 3983.46,1715.53 3985.45,1712.34 3987.45,1707.16 3990.04,1704.56 3991.64,1701.77 3995.03,1699.58 3996.22,1698.38 3997.02,1697.98 4003.01,1694.79 4005.8,1693.59 4015.77,1693.19 4023.75,1693.59 4024.95,1693.99 4027.15,1694.59 4029.54,1696.18 4034.53,1697.98 4035.92,1698.98 4036.32,1699.77 4036.92,1700.37 4039.71,1701.97 4041.51,1703.76 4041.91,1704.56 4042.51,1705.16 4043.3,1705.56 4044.3,1706.56 4046.3,1710.15 4047.49,1711.35 4047.89,1712.14 4048.69,1714.14 4049.29,1716.73 4050.29,1718.93 4051.88,1724.51 4052.28,1726.11 4052.08,1840.81 4053.08,1842.21 4055.27,1842.81 4061.66,1842.41 4103.75,1842.61 4104.95,1841.81 4105.34,1840.22 4105.15,1834.43 4105.34,1660.68 4104.95,1659.48 4105.34,1654.29 4104.35,1652.1 4102.75,1651.7 4095.17,1652.1 4054.48,1652.5 4053.88,1653.09 4053.48,1654.69 4053.68,1660.08 4053.48,1672.64 4053.88,1673.84 4053.48,1681.02 4052.48,1682.02 4049.69,1681.62 4048.29,1680.22 4047.69,1677.63 4046.89,1675.64 4046.3,1675.04 4045.9,1674.24 4044.3,1672.64 4042.31,1669.05 4041.31,1668.06 4040.51,1667.66 4039.51,1666.66 4039.11,1665.86 4037.72,1664.47 4036.92,1664.07 4033.73,1660.87 4032.93,1660.48 4030.14,1658.88 4028.14,1656.88 4026.15,1656.09 4021.76,1653.69 4019.76,1652.89 4018.17,1652.5 4015.38,1652.1 4013.78,1651.7 4011.19,1650.7 4008.99,1649.7 4007.4,1649.3 4002.41,1648.71 3985.45,1648.51 3984.26,1648.91 3981.26,1649.5 3979.67,1649.9 3977.87,1650.5 3975.68,1651.1 3973.68,1651.5 3972.09,1651.9 3969.69,1652.3 3968.1,1652.7 3967.9,1652.89
  region: 3884.91,1904.65 3896.68,1904.85 3898.67,1904.05 3899.47,1903.25 3899.87,1901.66 3899.67,1896.27 3899.87,1660.28 3899.47,1659.08 3899.87,1655.09 3899.47,1653.09 3898.87,1652.5 3895.68,1651.7 3890.5,1652.1 3851.2,1651.9 3849.2,1652.7 3848.4,1653.49 3848,1655.09 3848.4,1660.28 3848.2,1901.86 3848.8,1903.25 3850.2,1904.65 3852.99,1905.05 3856.98,1904.65 3884.51,1904.65
  region: 142 vertices and 2 holes, not listed, extent 3630.96,1651.7 3826.86,1905.05
  region: 343 vertices and 0 holes, not listed, extent 4056.67,1542.78 4382.63,1889.49
  region: 594 vertices and 0 holes, not listed, extent 4313.21,1543.18 4639.18,1908.24
GND1 (plane layer: these items are gaps in the copper):
  region: 4545,4910 4545,4660 3815,4660 3815,4910
  lines w6: 3762.11,2746.79 3762.11,3550 4291.35,3550 4321.03,3520.32 4321.65,3520.32 4372.38,3469.59 4372.38,2729.85 4335.17,2692.65 4334.56,2692.65 4255.24,2613.33 4255.24,2613.02 4251.55,2609.33 4251.55,2501.55 4250.8,2500.8 3997.28,2500.8 3997.28,2577.72 3975,2600 3975,2660 3955,2680 3828.9,2680 3823.3,2685.61 3823.3,2685.76 3779.4,2729.65 3779.1,2729.65 3766.73,2742.02 3766.73,2742.17 3762.11,2746.79
PWR (plane layer: these items are gaps in the copper):
  region: 4545,4910 4545,4660 3815,4660 3815,4910
  lines w6: 3996.31,2479.96 3996.36,2480.01 3996.36,2486.11 3996.54,2486.29 4254.73,2486.29 4254.55,2486.11 4254.55,2287.41 4274.18,2267.78 4274.25,2267.78 4301.13,2240.91 4301.2,2240.91 4347.32,2194.78 4347.62,2194.78 4388.61,2153.79 ; 3996.3,2481.03 3996.3,2271.3 3980,2255 3920,2195 3860,2135 3860,2115 3860,1935 3970,1935 4400,1935 4400,2142.4 4388.61,2153.79 ; 4388.61,2153.79 4388.61,2153.79 ; 3030,4225 3030,4575 3040,4585 3095,4640 3210,4640 3695,4640 3815,4520 4195,4520 4320,4395 4575,4395 4725,4395 4725,4305 4725,4240 4735,4230 4840,4230 4840.5,4230 4874.27,4263.77 4943.77,4263.77 4945,4265 4945,4070 4930,4055 4915,4055 4900,4040 4900,3966.37 5021.37,3845 5117.2,3845 5252.2,3710 5385.86,3710 5385.86,3580.86 5380,3575 5208.91,3575 5167.85,3616.06 5023.94,3616.06 4875,3765 4875,3770 4845,3800 4720,3800 4565,3955 4465,4055 3825,4055 3640,4240 3496.03,4383.97 3223.17,4383.97 3223.17,4281.83 3245,4260 3255,4260 3260,4255 3260,4225 3255,4220 3255,4190 3165,4190 3155,4200 3055,4200 3050,4205 3030,4225 ; 3760,2750 3760,2780 3760,3550 3800,3550 4291.3,3550 4372.35,3468.95 4372.35,3452.72 4372.35,2730.08 4362.42,2720.15 4361.36,2720.15 4271,2629.79 4269.79,2629.79 4250,2610 4250,2500 4000,2500 4000,2575 3990,2585 3980,2595 3980,2655 3955,2680 3830,2680 3810,2700 3760,2750 ; 4290,2295 4310,2275 4310,2235 4340,2205 4340.06,2205 4374.85,2170.21 4374.85,2169.9 4399.75,2145 4498.39,2145 4744.74,2391.35 4968.65,2391.35 5061.35,2391.35 5090,2420 5090,2640 5085.88,2644.12 4800.88,2644.12 4700,2745 4700,2780 4690,2790 4630,2790 4565,2790 4505,2850 4470,2850 4446.75,2826.75 4446.75,2716.75 4405,2675 4405,2535 4400,2530 4400,2500 4340,2440 4290,2440 4290,2295
GND2 (plane layer: these items are gaps in the copper):
  region: 4545,4910 4545,4660 3815,4660 3815,4910
  region: 4545,4910 4545,4660 3815,4660 3815,4910
  lines w6: 5430,3250 5410,3230 5060,3230 5030,3260 5030,3265 4975,3320 4915,3320 4900,3335 4900,3425 4915,3440 5030,3440 5170,3440 5205,3475 5205,3480 5205,4335 5197.85,4327.85 4259.35,4327.85 4259.35,4340.95 4259.04,4341.27 4259.04,4425.96 4201.87,4483.13 3631.87,4483.13 3580,4535 3580,4645 3623.07,4688.07 4008.07,4688.07 4008.71,4687.42 4357.58,4687.42 4405,4640 4540,4505 5380,4505 5430,4455 ; 3760,2745 3760,3550 4290,3550 4305,3535 4310,3535 4375,3470 4375,3390 4375,2735 4330,2690 4255,2615 4255,2505 4250,2500 4000,2500 4000,2580 3980,2600 3980,2655 3955,2680 3825,2680 3760,2745

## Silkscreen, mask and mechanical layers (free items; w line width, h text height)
Top Overlay:
  drawing of 30 lines, arcs and shapes, not listed
  text "BOOT" at 3115,2990.89 h60
  text "RESET" at 4952.29,2990.22 h60
  text "BluAX V1.1.1" at 4323.72,755.12 h60 r45
Bottom Overlay:
  circle w5: c4475,4385 r2.45
  circle w5: c4959.17,4580.51 r2.45
  circle w5: c2935,2565 r2.45
  circle w5: c5259.79,4338.69 r2.45
  circle w5: c4779.17,4578.24 r2.45
  circle w5: c3387.04,3985.21 r2.45
  circle w5: c5224.4,3846.61 r2.45
Top Solder:
  drawing of 5 lines, arcs and shapes, not listed
Dimensions:
  lines w8: 3296.18,1576.14 4945.79,1576.14 4945.79,3225.75 3296.18,3225.75 3296.18,1576.14 ; 3463.5,1743.46 4762.72,1743.46 4762.72,3042.68 3463.5,3042.68 3463.5,1743.46
Dimensions (Mech34):
  circle w1: c4945.79,3225.75 r137.8
  circle w1: c3296.18,3225.75 r137.8
  circle w1: c4760,3035 r137.8
  circle w1: c3465,3050 r137.8
  circle w1: c3295,1580 r137.8
  circle w1: c3463.5,1743.46 r137.8
  circle w1: c4762.72,1743.46 r137.8
  circle w1: c4945.79,1576.14 r137.8
  lines w8: 2806.8,4825.26 2806.8,1833.2 3945,695 4295,695 4350,750 4535,935 4625,1025 5430,1830 5430,4830 5350,4910 2892.37,4910 2807.63,4825.26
